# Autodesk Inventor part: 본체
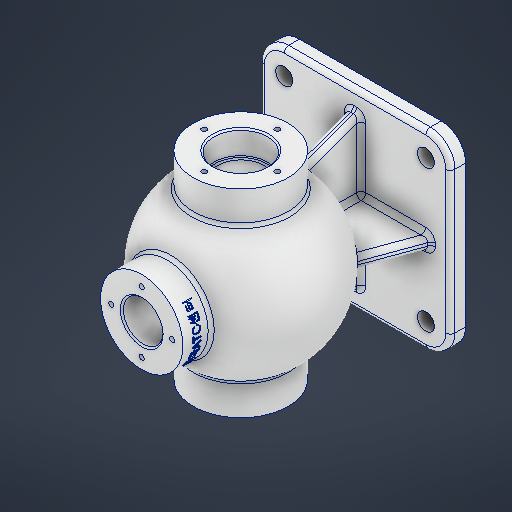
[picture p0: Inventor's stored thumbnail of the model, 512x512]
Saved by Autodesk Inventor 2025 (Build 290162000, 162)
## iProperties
Created: 2025-08
Part Number: 본체
Material: 알루미늄 6061
Document SubType Name: Modeling
Designer: infra10
Density: 2.7 g/cm^3
Appearance: 알루미늄 - 평지
Mass: 1525.62 g
Surface Area: 1200.53 cm^2
Volume: 565.046 cm^3
Author: infra10
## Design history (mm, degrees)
sketch "스케치1"
  geometry: L1 (-62.5, -62.5)-(62.5, -62.5); L2 (62.5, -62.5)-(62.5, 62.5); L3 (62.5, 62.5)-(-62.5, 62.5); L4 (-62.5, 62.5)-(-62.5, -62.5); L5 (-62.5, -62.5)-(62.5, 62.5); L6 (62.5, -62.5)-(-62.5, 62.5); 1 further point
  constraints: 12 end point, 2 midpoint, 2 parallel, 1 horizontal, 1 perpendicular
  dimensions: "d0" = 125 distance of L3.end L2.end; "d1" = 125 distance of L2.end L1.end
extrude "돌출1" new body sketch "스케치1" distance "d2" = 10; taper "d3" = 0 deg
node "작업 평면1"
sketch "스케치2"
  geometry: L1 (62.5, -62.5)-(-62.5, -62.5) reference; L2 (0, 0)-(0, 54); L3 (0, 54)-(0, -54); A1 r 54 centre (0, 0) between (0, -54) and (0, 54); A2 r 44 centre (0, 0) between (0, -44) and (0, 44); 3 further points
  constraints: 4 end point, 4 point on circle, 3 point on line, 2 centre point, 2 coincident, 1 midpoint, 1 vertical
  dimensions: "d5" = 108 diameter of A1; "d7" = 88 diameter of A2
revolve "회전1" sketch "스케치2" stored, may be unused: angle "d6" = 360 deg
node "작업 평면2"
sketch "스케치4"
  geometry: C1 r 54 at (0, 85) reference; C2 r 31 at (0, 85); 1 further point
  constraints: 1 centre point, 1 coincident
  dimensions: "d9" = 62 diameter of C2
extrude "돌출2" join sketch "스케치4" stored distance "d10" = 10; taper "d11" = 0 deg
node "작업 평면3"
sketch "스케치5"
  geometry: C1 r 31 at (0, 85) reference; 1 further point
extrude "돌출3" join sketch "스케치5" stored distance "d13" = 10; taper "d14" = 0 deg
sketch "스케치6"
  geometry: L1 (62.5, 0)-(62.5, 10) reference; L2 (62.5, 10)-(50.5, 10); L3 (-62.5, 10)-(62.5, 10) reference; L4 (50.5, 10)-(37.385, 46.034); L5 (-62.5, 10)-(-50.5, 10); L6 (-50.5, 10)-(-37.385, 46.034); A1 r 54 centre (0, 85) between (44.215, 116) and (44.215, 54) reference; 1 further point
  constraints: 8 end point, 2 point on circle, 2 point on line
  dimensions: "d15" = 12 distance of L1.end L2.end; "d16" = 110 deg angle of L2 L4; "d17" = 12 distance of L3.start L5.end; "d18" = 110 deg angle of L6 L5
extrude "돌출4" join sketch "스케치6" stored distance "d19" = 8; taper "d20" = 0 deg
sketch "스케치7"
  geometry: L1 (-62.5, 10)-(-50.5, 10); L2 (-62.5, 10)-(62.5, 10) reference; L3 (-50.5, 10)-(-37.385, 46.034); L4 (62.5, 10)-(50.5, 10); L5 (62.5, 0)-(62.5, 10) reference; L6 (62.5, 10)-(50.5, 10); L7 (50.5, 10)-(37.385, 46.034); 4 further points
  constraints: 10 end point, 2 point on line, 1 collinear, 4 other
  dimensions: "d21" = 12 distance of L1.start L1.end; "d22" = 110 deg angle of L3 L1; "d24" = 12 distance of L2.end L4.end; "d25" = 110 deg angle of L6 L7
extrude "돌출5" join sketch "스케치7" stored distance "d26" = 8; taper "d27" = 0 deg
node "작업 평면4"
sketch "스케치8"
  geometry: L1 (0, -37.385)-(0, 0) reference; C1 r 27 at (0, 0)
  constraints: 1 centre point, 1 coincident
  dimensions: "d29" = 54 diameter of C1
extrude "돌출6" join sketch "스케치8" stored distance "d30" = 8; taper "d31" = 0 deg
sketch "스케치9"
  geometry: C1 r 31 at (0, 0) reference; 2 further points
  constraints: 1 coincident
hole "구멍1" sketch "스케치9" at (0, 0) diameter "d32" = 30; stored, may be unused: countersink angle "d36" = 90 deg, drill point angle "d38" = 118 deg; dims "d33" = 6, "d34" = 35, "d35" = 16, "d37" = 30
sketch "스케치10"
  geometry: C1 r 31 at (0, 0) reference; 2 further points
  constraints: 1 coincident
hole "구멍2" sketch "스케치10" at (0, 0) diameter "d39" = 30; stored, may be unused: countersink angle "d43" = 90 deg, drill point angle "d45" = 118 deg; dims "d40" = 6, "d41" = 35, "d42" = 16, "d44" = 30
sketch "스케치11"
  geometry: 2 further points
  constraints: 1 coincident
hole "구멍3" sketch "스케치11" at (0, 0) diameter "d46" = 26; stored, may be unused: countersink angle "d50" = 90 deg, drill point angle "d52" = 118 deg; dims "d47" = 6, "d48" = 35, "d49" = 16, "d51" = 40
sketch "스케치12"
  geometry: L1 (46.5, 46.5)-(-46.5, 46.5); L2 (-46.5, 46.5)-(-46.5, -46.5); L3 (-46.5, -46.5)-(46.5, -46.5); L4 (46.5, -46.5)-(46.5, 46.5); L5 (46.5, 46.5)-(-46.5, -46.5); L6 (-46.5, 46.5)-(46.5, -46.5); 1 further point
  constraints: 12 end point, 2 midpoint, 2 parallel, 1 horizontal, 1 perpendicular
  dimensions: "d53" = 93 distance of L3.end L2.end; "d54" = 93 distance of L2.end L1.end
hole "구멍4" sketch "스케치12" at (46.5, -46.5), (46.5, 46.5), (-46.5, 46.5), (-46.5, -46.5) diameter "d55" = 11; stored, may be unused: countersink angle "d59" = 90 deg, drill point angle "d61" = 118 deg; dims "d56" = 6, "d57" = 4, "d58" = 2, "d60" = 40
sketch "스케치13"
  geometry: L1 (0, 0)-(0, -24); L2 (0, 0)-(-24, 0); L3 (0, 0)-(0, 24); L4 (0, 0)-(24, 0); C1 r 31 at (0, 0) reference; A1 r 24 centre (0, 0) between (0, -24) and (-24, 0); 1 further point
  constraints: 8 end point, 4 point on circle, 2 point on line, 1 centre point, 1 coincident, 1 perpendicular, 1 vertical
  dimensions: "d63" = 48 diameter of A1
hole "구멍5" sketch "스케치13" at (0, -24), (24, 0), (0, 24), (-24, 0) diameter "d64" = 3.242; stored, may be unused: countersink angle "d68" = 90 deg, drill point angle "d70" = 118 deg; dims "d65" = 12, "d66" = 4, "d67" = 2, "d69" = 15
sketch "스케치14"
  geometry: C1 r 1.621 at (-24, 0) reference; C2 r 1.621 at (0, 24) reference; C3 r 1.621 at (0, -24) reference; C4 r 1.621 at (24, 0) reference; 1 further point
hole "구멍6" sketch "스케치14" at (0, 24), (-24, 0), (0, -24), (24, 0) diameter "d71" = 3.242; stored, may be unused: countersink angle "d75" = 90 deg, drill point angle "d77" = 118 deg; dims "d72" = 12, "d73" = 4, "d74" = 2, "d76" = 15
sketch "스케치15"
  geometry: L1 (0, 0)-(-4, -4) reference; L2 (0, 0)-(-37.385, 0) reference; L3 (0, 0)-(0, 20); L4 (0, 0)-(0, 37.385) reference; L5 (0, 0)-(-20, 0); L6 (0, 0)-(20, 0); L7 (0, 0)-(0, -20); A1 r 20 centre (0, 0) between (0, 20) and (-20, 0)
  constraints: 8 end point, 4 point on circle, 3 point on line, 1 centre point, 1 coincident, 1 perpendicular
  dimensions: "d78" = 40 diameter of A1
hole "구멍7" sketch "스케치15" at (0, 20), (-20, 0), (0, -20), (20, 0) diameter "d79" = 3.242; stored, may be unused: countersink angle "d83" = 90 deg, drill point angle "d85" = 118 deg; dims "d80" = 9, "d81" = 4, "d82" = 2, "d84" = 11
node "작업 평면5"
sketch "스케치16"
  geometry: L1 (-12.632, 144.777)-(12.632, 144.777); L2 (12.632, 144.777)-(12.632, 137.223); L3 (12.632, 137.223)-(-12.632, 137.223); L4 (-12.632, 137.223)-(-12.632, 144.777); L5 (27, 150)-(-27, 150) reference; L6 (65, 54)-(65, 116) reference; L7 (-65, 54)-(-65, 116) reference; 4 further points
  constraints: 3 midpoint, 1 parallel, 2 other
  dimensions: "d89" = 9 distance from line of L5 point (-12.632, 141); "d90" = 65 distance from line of L7 point (0, 144.777); "d91" = 52.36799 distance between parallel lines of L7 L4; "d92" = 5.22342 distance between parallel lines of L1 L5
feature "엠보싱1" sketch "스케치16" dims "d93" = 0.5, "d94" = 0
fillet "모깎기1" dims "d95" = 16
fillet "모깎기2" dims "d96" = 3
fillet "모깎기3" dims "d97" = 3
fillet "모깎기4" dims "d98" = 3
fillet "모깎기5" dims "d99" = 3
fillet "모깎기6" dims "d100" = 3
chamfer "모따기1" distance "d101" = 1; stored, may be unused: second distance "d102" = 2, angle "d103" = 45 deg
chamfer "모따기2" distance "d104" = 1; stored, may be unused: second distance "d105" = 2, angle "d106" = 45 deg
chamfer "모따기3" distance "d107" = 1; stored, may be unused: second distance "d108" = 2, angle "d109" = 45 deg
fillet "모깎기7" dims "d116" = 0.6
feature "С耀У耀Х耀Ч耀Щ耀Ы耀Э耀Я耀" dims "d0" = 125, "d1" = 125, "d2" = 10, "d3" = 0, "d4" = -85, "d5" = 108, "d6" = 360 deg, "d7" = 88, "d8" = 65, "d9" = 62, "d10" = 10, "d11" = 0, "d12" = -65, "d13" = 10, "d14" = 0, "d15" = 12, "d16" = 110 deg, "d17" = 12, "d18" = 110 deg, "d19" = 8, "d20" = 0, "d21" = 12, "d22" = 110 deg, "d24" = 12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
node "솔리드1"
feature "A9D066F2-1C7D-4E18-AEED-F7BC21143FA4" dims "d32" = 30, "d33" = 6, "d34" = 35, "d35" = 16, "d36" = 90 deg, "d37" = 30, "d38" = 118 deg
